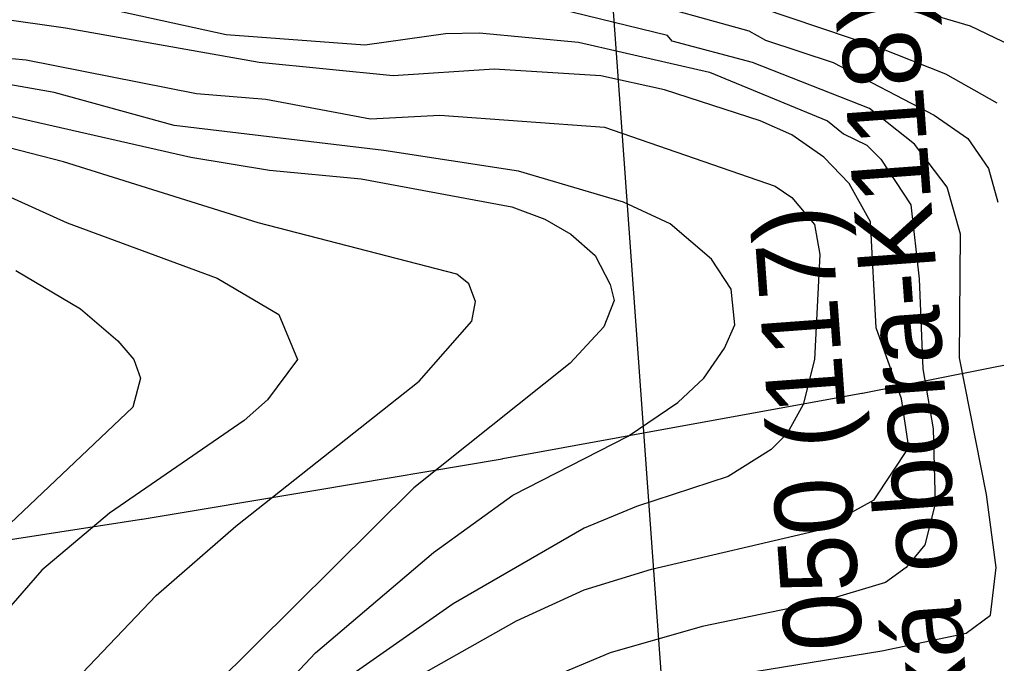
# Model space of a CAD drawing. Extents: x -758499 to -754160, y -1175205 to -1172032.
# Drawn here: x -757348.1 to -757197.5, y -1172996.9 to -1172897.7 of the extents above; entities that cross this region are included whole.
import ezdxf

# ---------------------------------------------------------------- set-up
doc = ezdxf.new("R2010")
doc.units = 0
for name, color, linetype in [('A102_LetVysk_op', 7, 'Continuous'), ('vrstevnice', 7, 'Continuous'), ('ÚSES NBK funkční', 7, 'Continuous')]:
    doc.layers.add(name, color=color, linetype=linetype)

msp = doc.modelspace()

# ---------------------------------------------------------------- linework, layer by layer
at = {"layer": 'A102_LetVysk_op'}
for p, q in [((-757218.14, -1172955.23), (-757190.36, -1172949.76)), ((-757246.25, -1172960.36), (-757218.26, -1172955.25)), ((-757218.26, -1172955.25), (-757218.14, -1172955.23)), ((-757273.58, -1172965.34), (-757246.25, -1172960.36)), ((-757302.4, -1172970.18), (-757273.7, -1172965.36)), ((-757273.7, -1172965.36), (-757273.58, -1172965.34)), ((-757329.17, -1172974.67), (-757302.4, -1172970.18)), ((-757357.3, -1172978.99), (-757329.28, -1172974.69)), ((-757329.28, -1172974.69), (-757329.17, -1172974.67))]:
    msp.add_line(p, q, dxfattribs=at)
at = {"layer": 'vrstevnice'}
for p, q in [((-757245.39, -1172885.7), (-757201.56, -1172898.63)), ((-757257.89, -1172887.72), (-757215.46, -1172902.01)), ((-757257.89, -1172887.72), (-757215.46, -1172902.01)), ((-757264.24, -1172891.47), (-757235.66, -1172899.41)), ((-757264.24, -1172891.47), (-757235.66, -1172899.41)), ((-757248.22, -1172900.13), (-757271.17, -1172894.5)), ((-757248.22, -1172900.13), (-757271.17, -1172894.5)), ((-757341.02, -1172898.98), (-757356.61, -1172896.81)), ((-757335.97, -1172895.66), (-757316.26, -1172899.98)), ((-757335.97, -1172895.66), (-757316.26, -1172899.98)), ((-757201.56, -1172898.63), (-757193.44, -1172902.52)), ((-757311.17, -1172904.32), (-757341.02, -1172898.98)), ((-757316.26, -1172899.98), (-757294.84, -1172901.57)), ((-757316.26, -1172899.98), (-757294.84, -1172901.57)), ((-757294.84, -1172901.57), (-757282.43, -1172899.84)), ((-757294.84, -1172901.57), (-757282.43, -1172899.84)), ((-757282.43, -1172899.84), (-757277.23, -1172899.7)), ((-757282.43, -1172899.84), (-757277.23, -1172899.7)), ((-757277.23, -1172899.7), (-757261.93, -1172901.14)), ((-757277.23, -1172899.7), (-757261.93, -1172901.14)), ((-757247.5, -1172901), (-757248.22, -1172900.13)), ((-757247.5, -1172901), (-757248.22, -1172900.13)), ((-757235.66, -1172899.41), (-757233.07, -1172900.85)), ((-757235.66, -1172899.41), (-757233.07, -1172900.85)), ((-757261.93, -1172901.14), (-757241.73, -1172905.76)), ((-757261.93, -1172901.14), (-757241.73, -1172905.76)), ((-757235.09, -1172904.32), (-757247.5, -1172901)), ((-757235.09, -1172904.32), (-757247.5, -1172901)), ((-757233.07, -1172900.85), (-757222.68, -1172904.32)), ((-757233.07, -1172900.85), (-757222.68, -1172904.32)), ((-757359.21, -1172902.73), (-757347.08, -1172903.88)), ((-757359.21, -1172902.73), (-757347.08, -1172903.88)), ((-757215.46, -1172902.01), (-757205.36, -1172906.05)), ((-757215.46, -1172902.01), (-757205.36, -1172906.05)), ((-757347.08, -1172903.88), (-757320.82, -1172909.08)), ((-757347.08, -1172903.88), (-757320.82, -1172909.08)), ((-757290.51, -1172906.34), (-757311.17, -1172904.32)), ((-757217.05, -1172911.39), (-757235.09, -1172904.32)), ((-757217.05, -1172911.39), (-757235.09, -1172904.32)), ((-757222.68, -1172904.32), (-757207.09, -1172912.4)), ((-757222.68, -1172904.32), (-757207.09, -1172912.4)), ((-757342.75, -1172908.93), (-757358.92, -1172906.05)), ((-757342.75, -1172908.93), (-757358.92, -1172906.05)), ((-757274.92, -1172905.33), (-757290.51, -1172906.34)), ((-757258.47, -1172906.34), (-757274.92, -1172905.33)), ((-757241.73, -1172905.76), (-757223.54, -1172913.26)), ((-757241.73, -1172905.76), (-757223.54, -1172913.26)), ((-757205.36, -1172906.05), (-757197.42, -1172910.52)), ((-757205.36, -1172906.05), (-757197.42, -1172910.52)), ((-757248.65, -1172908.5), (-757258.47, -1172906.34)), ((-757324.28, -1172913.99), (-757342.75, -1172908.93)), ((-757324.28, -1172913.99), (-757342.75, -1172908.93)), ((-757320.82, -1172909.08), (-757310.14, -1172909.94)), ((-757320.82, -1172909.08), (-757310.14, -1172909.94)), ((-757233.93, -1172913.26), (-757248.65, -1172908.5)), ((-757310.14, -1172909.94), (-757293.97, -1172912.98)), ((-757310.14, -1172909.94), (-757293.97, -1172912.98)), ((-757356.03, -1172911.1), (-757321.68, -1172918.89)), ((-757356.03, -1172911.1), (-757321.68, -1172918.89)), ((-757210.12, -1172916.87), (-757217.05, -1172911.39)), ((-757210.12, -1172916.87), (-757217.05, -1172911.39)), ((-757293.97, -1172912.98), (-757283.29, -1172912.4)), ((-757293.97, -1172912.98), (-757283.29, -1172912.4)), ((-757283.29, -1172912.4), (-757257.89, -1172914.27)), ((-757283.29, -1172912.4), (-757257.89, -1172914.27)), ((-757229.03, -1172915.43), (-757233.93, -1172913.26)), ((-757223.54, -1172913.26), (-757221.09, -1172915.28)), ((-757223.54, -1172913.26), (-757221.09, -1172915.28)), ((-757207.09, -1172912.4), (-757201.89, -1172916.01)), ((-757207.09, -1172912.4), (-757201.89, -1172916.01)), ((-757291.95, -1172917.88), (-757324.28, -1172913.99)), ((-757291.95, -1172917.88), (-757324.28, -1172913.99)), ((-757257.89, -1172914.27), (-757231.62, -1172923.37)), ((-757257.89, -1172914.27), (-757231.62, -1172923.37)), ((-757341.31, -1172919.61), (-757355.16, -1172916.01)), ((-757341.31, -1172919.61), (-757355.16, -1172916.01)), ((-757224.12, -1172918.89), (-757229.03, -1172915.43)), ((-757221.09, -1172915.28), (-757217.48, -1172917.02)), ((-757221.09, -1172915.28), (-757217.48, -1172917.02)), ((-757201.89, -1172916.01), (-757198.72, -1172920.62)), ((-757201.89, -1172916.01), (-757198.72, -1172920.62)), ((-757271.17, -1172921.06), (-757291.95, -1172917.88)), ((-757271.17, -1172921.06), (-757291.95, -1172917.88)), ((-757217.48, -1172917.02), (-757215.32, -1172919.18)), ((-757217.48, -1172917.02), (-757215.32, -1172919.18)), ((-757205.07, -1172923.51), (-757210.12, -1172916.87)), ((-757205.07, -1172923.51), (-757210.12, -1172916.87)), ((-757311.29, -1172928.99), (-757341.31, -1172919.61)), ((-757311.29, -1172928.99), (-757341.31, -1172919.61)), ((-757321.68, -1172918.89), (-757309.56, -1172920.91)), ((-757321.68, -1172918.89), (-757309.56, -1172920.91)), ((-757220.22, -1172922.93), (-757224.12, -1172918.89)), ((-757215.32, -1172919.18), (-757210.7, -1172926.25)), ((-757215.32, -1172919.18), (-757210.7, -1172926.25)), ((-757309.56, -1172920.91), (-757295.41, -1172922.21)), ((-757309.56, -1172920.91), (-757295.41, -1172922.21)), ((-757255, -1172925.82), (-757271.17, -1172921.06)), ((-757255, -1172925.82), (-757271.17, -1172921.06)), ((-757198.72, -1172920.62), (-757197.27, -1172925.82)), ((-757198.72, -1172920.62), (-757197.27, -1172925.82)), ((-757295.41, -1172922.21), (-757272.18, -1172926.54)), ((-757295.41, -1172922.21), (-757272.18, -1172926.54)), ((-757231.62, -1172923.37), (-757229.03, -1172925.1)), ((-757231.62, -1172923.37), (-757229.03, -1172925.1)), ((-757216.9, -1172928.85), (-757220.22, -1172922.93)), ((-757203.05, -1172930.73), (-757205.07, -1172923.51)), ((-757203.05, -1172930.73), (-757205.07, -1172923.51)), ((-757351.15, -1172924.35), (-757340.73, -1172928.99)), ((-757229.03, -1172925.1), (-757225.56, -1172929.28)), ((-757229.03, -1172925.1), (-757225.56, -1172929.28)), ((-757272.18, -1172926.54), (-757267.13, -1172928.42)), ((-757272.18, -1172926.54), (-757267.13, -1172928.42)), ((-757247.79, -1172929.14), (-757255, -1172925.82)), ((-757247.79, -1172929.14), (-757255, -1172925.82)), ((-757210.7, -1172926.25), (-757209.4, -1172937.65)), ((-757210.7, -1172926.25), (-757209.4, -1172937.65)), ((-757267.13, -1172928.42), (-757263.09, -1172930.73)), ((-757267.13, -1172928.42), (-757263.09, -1172930.73)), ((-757340.73, -1172928.99), (-757317.64, -1172937.51)), ((-757280.69, -1172936.93), (-757311.29, -1172928.99)), ((-757280.69, -1172936.93), (-757311.29, -1172928.99)), ((-757241.44, -1172934.62), (-757247.79, -1172929.14)), ((-757241.44, -1172934.62), (-757247.79, -1172929.14)), ((-757225.56, -1172929.28), (-757224.7, -1172933.9)), ((-757225.56, -1172929.28), (-757224.7, -1172933.9)), ((-757216.04, -1172945.16), (-757216.9, -1172928.85)), ((-757263.09, -1172930.73), (-757259.33, -1172934.05)), ((-757263.09, -1172930.73), (-757259.33, -1172934.05)), ((-757203.19, -1172949.78), (-757203.05, -1172930.73)), ((-757203.19, -1172949.78), (-757203.05, -1172930.73)), ((-757259.33, -1172934.05), (-757257.02, -1172938.52)), ((-757259.33, -1172934.05), (-757257.02, -1172938.52)), ((-757238.41, -1172939.24), (-757241.44, -1172934.62)), ((-757238.41, -1172939.24), (-757241.44, -1172934.62)), ((-757224.7, -1172933.9), (-757225.56, -1172950.07)), ((-757224.7, -1172933.9), (-757225.56, -1172950.07)), ((-757348.67, -1172936.36), (-757338.71, -1172942.27)), ((-757348.67, -1172936.36), (-757338.71, -1172942.27)), ((-757317.64, -1172937.51), (-757308.12, -1172943.14)), ((-757278.82, -1172938.38), (-757280.69, -1172936.93)), ((-757278.82, -1172938.38), (-757280.69, -1172936.93)), ((-757209.4, -1172937.65), (-757208.82, -1172951.51)), ((-757209.4, -1172937.65), (-757208.82, -1172951.51)), ((-757277.81, -1172941.12), (-757278.82, -1172938.38)), ((-757277.81, -1172941.12), (-757278.82, -1172938.38)), ((-757257.02, -1172938.52), (-757256.45, -1172940.97)), ((-757257.02, -1172938.52), (-757256.45, -1172940.97)), ((-757237.83, -1172944.73), (-757238.41, -1172939.24)), ((-757237.83, -1172944.73), (-757238.41, -1172939.24)), ((-757338.71, -1172942.27), (-757332.94, -1172947.18)), ((-757338.71, -1172942.27), (-757332.94, -1172947.18)), ((-757278.38, -1172944.15), (-757277.81, -1172941.12)), ((-757278.38, -1172944.15), (-757277.81, -1172941.12)), ((-757256.45, -1172940.97), (-757258.03, -1172945.01)), ((-757256.45, -1172940.97), (-757258.03, -1172945.01)), ((-757308.12, -1172943.14), (-757305.23, -1172950.07)), ((-757286.47, -1172953.39), (-757278.38, -1172944.15)), ((-757286.47, -1172953.39), (-757278.38, -1172944.15)), ((-757258.03, -1172945.01), (-757263.23, -1172950.64)), ((-757258.03, -1172945.01), (-757263.23, -1172950.64)), ((-757239.42, -1172948.33), (-757237.83, -1172944.73)), ((-757239.42, -1172948.33), (-757237.83, -1172944.73)), ((-757212.14, -1172956.13), (-757216.04, -1172945.16)), ((-757332.94, -1172947.18), (-757330.48, -1172950.07)), ((-757332.94, -1172947.18), (-757330.48, -1172950.07)), ((-757242.59, -1172952.95), (-757239.42, -1172948.33)), ((-757242.59, -1172952.95), (-757239.42, -1172948.33)), ((-757199.01, -1172970.85), (-757203.19, -1172949.78)), ((-757199.01, -1172970.85), (-757203.19, -1172949.78)), ((-757330.48, -1172950.07), (-757329.47, -1172952.95)), ((-757330.48, -1172950.07), (-757329.47, -1172952.95)), ((-757305.23, -1172950.07), (-757309.85, -1172956.27)), ((-757263.23, -1172950.64), (-757287.33, -1172969.84)), ((-757263.23, -1172950.64), (-757287.33, -1172969.84)), ((-757225.56, -1172950.07), (-757227.29, -1172956.99)), ((-757225.56, -1172950.07), (-757227.29, -1172956.99)), ((-757208.82, -1172951.51), (-757207.23, -1172960.75)), ((-757208.82, -1172951.51), (-757207.23, -1172960.75)), ((-757329.47, -1172952.95), (-757330.63, -1172957.43)), ((-757329.47, -1172952.95), (-757330.63, -1172957.43)), ((-757314.75, -1172975.76), (-757286.47, -1172953.39)), ((-757314.75, -1172975.76), (-757286.47, -1172953.39)), ((-757246.63, -1172956.7), (-757242.59, -1172952.95)), ((-757246.63, -1172956.7), (-757242.59, -1172952.95)), ((-757309.85, -1172956.27), (-757313.45, -1172959.45)), ((-757254.28, -1172961.9), (-757246.63, -1172956.7)), ((-757254.28, -1172961.9), (-757246.63, -1172956.7)), ((-757227.29, -1172956.99), (-757229.75, -1172961.47)), ((-757227.29, -1172956.99), (-757229.75, -1172961.47)), ((-757210.99, -1172963.63), (-757212.14, -1172956.13)), ((-757330.63, -1172957.43), (-757352.42, -1172978.06)), ((-757330.63, -1172957.43), (-757352.42, -1172978.06)), ((-757313.45, -1172959.45), (-757334.24, -1172973.73)), ((-757272.03, -1172970.99), (-757254.28, -1172961.9)), ((-757272.03, -1172970.99), (-757254.28, -1172961.9)), ((-757229.75, -1172961.47), (-757232.2, -1172963.92)), ((-757229.75, -1172961.47), (-757232.2, -1172963.92)), ((-757207.23, -1172960.75), (-757206.94, -1172972.29)), ((-757207.23, -1172960.75), (-757206.94, -1172972.29)), ((-757232.2, -1172963.92), (-757238.84, -1172968.11)), ((-757232.2, -1172963.92), (-757238.84, -1172968.11)), ((-757216.33, -1172971.71), (-757210.99, -1172963.63)), ((-757238.84, -1172968.11), (-757252.98, -1172972.72)), ((-757238.84, -1172968.11), (-757252.98, -1172972.72)), ((-757287.33, -1172969.84), (-757322.4, -1173004.62)), ((-757287.33, -1172969.84), (-757322.4, -1173004.62)), ((-757197.56, -1172982.11), (-757199.01, -1172970.85)), ((-757197.56, -1172982.11), (-757199.01, -1172970.85)), ((-757284.3, -1172979.8), (-757272.03, -1172970.99)), ((-757284.3, -1172979.8), (-757272.03, -1172970.99)), ((-757224.7, -1172976.33), (-757216.33, -1172971.71)), ((-757206.94, -1172972.29), (-757208.53, -1172978.64)), ((-757206.94, -1172972.29), (-757208.53, -1172978.64)), ((-757334.24, -1172973.73), (-757344.63, -1172982.54)), ((-757252.98, -1172972.72), (-757261.07, -1172976.04)), ((-757252.98, -1172972.72), (-757261.07, -1172976.04)), ((-757327.02, -1172986.44), (-757314.75, -1172975.76)), ((-757327.02, -1172986.44), (-757314.75, -1172975.76)), ((-757261.07, -1172976.04), (-757281.27, -1172987.73)), ((-757261.07, -1172976.04), (-757281.27, -1172987.73)), ((-757250.67, -1172982.39), (-757224.7, -1172976.33)), ((-757302.49, -1172995.24), (-757284.3, -1172979.8)), ((-757302.49, -1172995.24), (-757284.3, -1172979.8)), ((-757208.53, -1172978.64), (-757211.42, -1172982.11)), ((-757208.53, -1172978.64), (-757211.42, -1172982.11)), ((-757344.63, -1172982.54), (-757356.17, -1172995.67)), ((-757261.07, -1172985.57), (-757250.67, -1172982.39)), ((-757211.42, -1172982.11), (-757214.59, -1172984.41)), ((-757211.42, -1172982.11), (-757214.59, -1172984.41)), ((-757198.43, -1172989.47), (-757197.56, -1172982.11)), ((-757198.43, -1172989.47), (-757197.56, -1172982.11)), ((-757214.59, -1172984.41), (-757224.7, -1172987.45)), ((-757214.59, -1172984.41), (-757224.7, -1172987.45)), ((-757271.46, -1172990.33), (-757261.07, -1172985.57)), ((-757339.43, -1172999.42), (-757327.02, -1172986.44)), ((-757339.43, -1172999.42), (-757327.02, -1172986.44)), ((-757224.7, -1172987.45), (-757242.88, -1172991.2)), ((-757224.7, -1172987.45), (-757242.88, -1172991.2)), ((-757281.27, -1172987.73), (-757296.14, -1172998.13)), ((-757281.27, -1172987.73), (-757296.14, -1172998.13)), ((-757287.04, -1172999.14), (-757271.46, -1172990.33)), ((-757202.18, -1172992.21), (-757198.43, -1172989.47)), ((-757202.18, -1172992.21), (-757198.43, -1172989.47)), ((-757242.88, -1172991.2), (-757257.02, -1172995.24)), ((-757242.88, -1172991.2), (-757257.02, -1172995.24)), ((-757215.17, -1172994.95), (-757202.18, -1172992.21)), ((-757215.17, -1172994.95), (-757202.18, -1172992.21)), ((-757245.48, -1172999.86), (-757215.17, -1172994.95)), ((-757245.48, -1172999.86), (-757215.17, -1172994.95)), ((-757313.74, -1173007.22), (-757302.49, -1172995.24)), ((-757313.74, -1173007.22), (-757302.49, -1172995.24)), ((-757257.02, -1172995.24), (-757271.17, -1173001.16)), ((-757257.02, -1172995.24), (-757271.17, -1173001.16))]:
    msp.add_line(p, q, dxfattribs=at)
at = {"layer": 'ÚSES NBK funkční'}
msp.add_line((-757259.28, -1172858.71), (-757239.9, -1173127.24), dxfattribs=at)

# ---------------------------------------------------------------- texts
for s, p in [('(Hlubocká obora-K118)', (-757197.8, -1173059.01)), ('NBK 050 (117)', (-757215.35, -1173031.88))]:
    msp.add_text(s, height=12, rotation=94.1751, dxfattribs=at).set_placement(p)

doc.saveas('drawing.dxf')
